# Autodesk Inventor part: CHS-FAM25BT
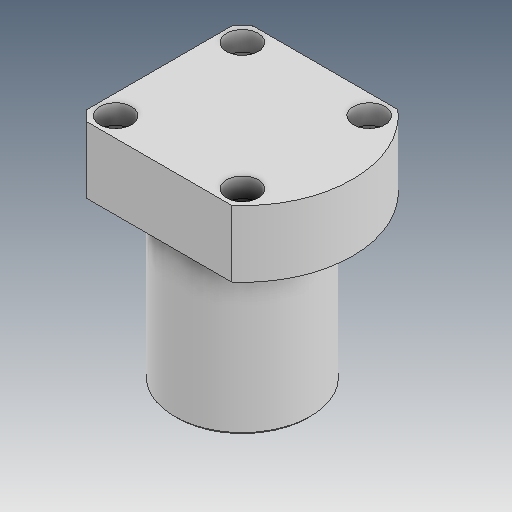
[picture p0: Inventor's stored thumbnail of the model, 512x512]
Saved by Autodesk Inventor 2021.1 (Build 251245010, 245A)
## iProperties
Created: 2019-04
Part Number: CHS-FAM25BT
Material: Ogólny
Document SubType Name: Modeling
Designer: user
Density: 1 g/cm^3
Appearance: Domyślna
Author: user
Revision Number: ÈÎºÎ
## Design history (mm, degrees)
feature "ÊäÈë1"
node "Bryła1"
